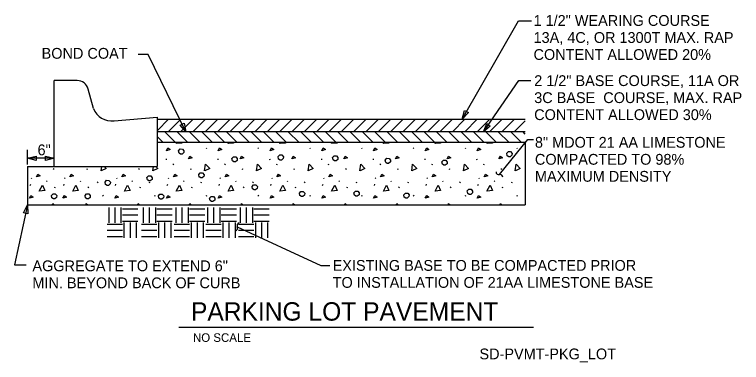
# Model space of a CAD drawing. Extents: x 9880 to 9950.2, y 9968.4 to 10002.
import ezdxf

# ---------------------------------------------------------------- set-up
doc = ezdxf.new("R2010")
doc.units = 0
for name, color, linetype in [('Default', 7, 'Continuous'), ('G-ANNO-TEXT', 7, 'Continuous'), ('G-DETL-LINE', 7, 'Continuous'), ('G-DETL-OTLN', 7, 'Continuous'), ('G-DETL-PATT', 7, 'Continuous')]:
    doc.layers.add(name, color=color, linetype=linetype)

# ---------------------------------------------------------------- blocks, each defined once
blk = doc.blocks.new('TERARR')
at = {"layer": 'Default'}
blk.add_lwpolyline([(-0.667, 0.167), (0, 0), (-0.667, -0.167)], close=True, dxfattribs=at)

msp = doc.modelspace()

# ---------------------------------------------------------------- linework, layer by layer
at = {"layer": 'G-ANNO-TEXT'}
for p, q in [((9881.221, 9987.543), (9881.221, 9988.941)), ((9883.799, 9988.139), (9881.22, 9988.139)), ((9895.832, 9971.824), (9930.089, 9971.824))]:
    msp.add_line(p, q, dxfattribs=at)
for points in [[(9923.211, 9991.928), (9928.665, 10001.42), (9929.9, 10001.42)], [(9896.528, 9990.678), (9892.894, 9998.162), (9891.91, 9998.162)], [(9925.285, 9990.677), (9928.691, 9995.651), (9929.853, 9995.651)]]:
    msp.add_lwpolyline(points, dxfattribs=at)
for points in [[(9923.807, 9992.546), (9923.211, 9991.928), (9923.446, 9992.754)], [(9896.352, 9991.519), (9896.528, 9990.678), (9895.977, 9991.337)], [(9925.927, 9991.247), (9925.285, 9990.677), (9925.584, 9991.483)]]:
    msp.add_lwpolyline(points, close=True, dxfattribs=at)
at = {"layer": 'G-DETL-LINE'}
for p, q in [((9893.766, 9991.898), (9929.301, 9991.898)), ((9929.301, 9990.678), (9893.766, 9990.678)), ((9929.301, 9989.646), (9893.766, 9989.646)), ((9929.301, 9989.646), (9929.301, 9983.643)), ((9881.221, 9987.336), (9883.811, 9987.343)), ((9881.221, 9987.336), (9881.221, 9983.637)), ((9881.234, 9983.643), (9929.301, 9983.643))]:
    msp.add_line(p, q, dxfattribs=at)
for points in [[(9926.807, 9986.558), (9929.565, 9989.95), (9930.084, 9989.95)], [(9881.221, 9983.637), (9879.972, 9977.829), (9881.089, 9977.829)], [(9901.491, 9981.502), (9909.552, 9977.758), (9910.411, 9977.758)]]:
    msp.add_lwpolyline(points, dxfattribs=at)
msp.add_lwpolyline([(9880.842, 9982.866), (9881.221, 9983.637), (9881.249, 9982.778)], close=True, dxfattribs=at)
msp.add_lwpolyline([(9880.842, 9982.866), (9881.221, 9983.637), (9881.249, 9982.778)], close=True, dxfattribs=at)
for centre, start, end in [((9926.744, 9986.811), 177.75583, 284.01603), ((9926.87, 9986.305), 357.75583, 104.01603), ((9901.72, 9981.625), 101.95462, 208.21482), ((9901.261, 9981.379), 281.95462, 28.21482)]:
    msp.add_arc(centre, 0.26, start, end, dxfattribs=at)
at = {"layer": 'G-DETL-OTLN'}
for p, q in [((9886.017, 9995.637), (9883.811, 9995.637)), ((9883.811, 9987.343), (9883.811, 9995.637)), ((9887.605, 9992.951), (9887.082, 9994.828)), ((9889.593, 9991.765), (9893.764, 9992.112)), ((9893.764, 9992.112), (9893.764, 9987.343)), ((9883.811, 9987.343), (9893.764, 9987.343))]:
    msp.add_line(p, q, dxfattribs=at)
for centre, radius, start, end in [((9886.017, 9994.531), 1.106, 15.57142, 90), ((9889.317, 9993.56), 1.816, 199.56291, 278.7552)]:
    msp.add_arc(centre, radius, start, end, dxfattribs=at)
at = {"layer": 'G-DETL-PATT'}
for p, q in [((9893.766, 9990.82), (9894.843, 9991.898)), ((9894.817, 9990.678), (9896.037, 9991.898)), ((9896.01, 9990.678), (9897.23, 9991.898)), ((9897.203, 9990.678), (9898.423, 9991.898)), ((9898.397, 9990.678), (9899.616, 9991.898)), ((9899.59, 9990.678), (9900.809, 9991.898)), ((9900.783, 9990.678), (9902.002, 9991.898)), ((9901.976, 9990.678), (9903.196, 9991.898)), ((9903.169, 9990.678), (9904.389, 9991.898)), ((9904.362, 9990.678), (9905.582, 9991.898)), ((9905.556, 9990.678), (9906.775, 9991.898)), ((9906.749, 9990.678), (9907.968, 9991.898)), ((9907.942, 9990.678), (9909.161, 9991.898)), ((9909.135, 9990.678), (9910.355, 9991.898)), ((9910.328, 9990.678), (9911.548, 9991.898)), ((9911.521, 9990.678), (9912.741, 9991.898)), ((9912.714, 9990.678), (9913.934, 9991.898)), ((9913.908, 9990.678), (9915.127, 9991.898)), ((9915.101, 9990.678), (9916.32, 9991.898)), ((9916.294, 9990.678), (9917.514, 9991.898)), ((9917.487, 9990.678), (9918.707, 9991.898)), ((9918.68, 9990.678), (9919.9, 9991.898)), ((9919.873, 9990.678), (9921.093, 9991.898)), ((9921.066, 9990.678), (9922.286, 9991.898)), ((9922.26, 9990.678), (9923.479, 9991.898)), ((9923.453, 9990.678), (9924.672, 9991.898)), ((9924.646, 9990.678), (9925.866, 9991.898)), ((9925.839, 9990.678), (9927.059, 9991.898)), ((9927.032, 9990.678), (9928.252, 9991.898)), ((9928.225, 9990.678), (9929.301, 9991.753)), ((9894.325, 9989.646), (9893.766, 9990.206)), ((9895.518, 9989.646), (9894.486, 9990.678)), ((9896.712, 9989.646), (9895.679, 9990.678)), ((9897.905, 9989.646), (9896.873, 9990.678)), ((9899.098, 9989.646), (9898.066, 9990.678)), ((9900.291, 9989.646), (9899.259, 9990.678)), ((9901.484, 9989.646), (9900.452, 9990.678)), ((9902.677, 9989.646), (9901.645, 9990.678)), ((9903.871, 9989.646), (9902.838, 9990.678)), ((9905.064, 9989.646), (9904.032, 9990.678)), ((9906.257, 9989.646), (9905.225, 9990.678)), ((9907.45, 9989.646), (9906.418, 9990.678)), ((9908.643, 9989.646), (9907.611, 9990.678)), ((9909.836, 9989.646), (9908.804, 9990.678)), ((9911.03, 9989.646), (9909.997, 9990.678)), ((9912.223, 9989.646), (9911.19, 9990.678)), ((9913.416, 9989.646), (9912.384, 9990.678)), ((9914.609, 9989.646), (9913.577, 9990.678)), ((9915.802, 9989.646), (9914.77, 9990.678)), ((9916.995, 9989.646), (9915.963, 9990.678)), ((9918.188, 9989.646), (9917.156, 9990.678)), ((9919.382, 9989.646), (9918.349, 9990.678)), ((9920.575, 9989.646), (9919.543, 9990.678)), ((9921.768, 9989.646), (9920.736, 9990.678)), ((9922.961, 9989.646), (9921.929, 9990.678)), ((9924.154, 9989.646), (9923.122, 9990.678)), ((9925.347, 9989.646), (9924.315, 9990.678)), ((9926.541, 9989.646), (9925.508, 9990.678)), ((9927.734, 9989.646), (9926.701, 9990.678)), ((9928.927, 9989.646), (9927.895, 9990.678)), ((9929.301, 9990.465), (9929.088, 9990.678)), ((9898.484, 9989.147), (9898.528, 9989.08)), ((9903.484, 9989.147), (9903.528, 9989.08)), ((9908.484, 9989.147), (9908.528, 9989.08)), ((9913.484, 9989.147), (9913.528, 9989.08)), ((9918.484, 9989.147), (9918.528, 9989.08)), ((9923.484, 9989.147), (9923.528, 9989.08)), ((9928.484, 9989.147), (9928.528, 9989.08)), ((9894.606, 9988.082), (9894.617, 9987.982)), ((9895.298, 9987.493), (9895.343, 9987.593)), ((9899.606, 9988.082), (9899.617, 9987.982)), ((9900.298, 9987.493), (9900.343, 9987.593)), ((9904.606, 9988.082), (9904.617, 9987.982)), ((9905.298, 9987.493), (9905.343, 9987.593)), ((9909.606, 9988.082), (9909.617, 9987.982)), ((9910.298, 9987.493), (9910.343, 9987.593)), ((9914.606, 9988.082), (9914.617, 9987.982)), ((9915.298, 9987.493), (9915.343, 9987.593)), ((9919.606, 9988.082), (9919.617, 9987.982)), ((9920.298, 9987.493), (9920.343, 9987.593)), ((9924.606, 9988.082), (9924.617, 9987.982)), ((9925.298, 9987.493), (9925.343, 9987.593)), ((9883.75, 9987.038), (9883.795, 9987.138)), ((9886.985, 9987.038), (9887.03, 9987.138)), ((9891.985, 9987.038), (9892.03, 9987.138)), ((9896.985, 9987.038), (9897.03, 9987.138)), ((9901.985, 9987.038), (9902.03, 9987.138)), ((9906.985, 9987.038), (9907.03, 9987.138)), ((9911.985, 9987.038), (9912.03, 9987.138)), ((9916.985, 9987.038), (9917.03, 9987.138)), ((9921.985, 9987.038), (9922.03, 9987.138)), ((9926.985, 9987.038), (9927.03, 9987.138)), ((9881.576, 9986.25), (9881.621, 9986.183)), ((9884.811, 9986.25), (9884.856, 9986.183)), ((9889.811, 9986.25), (9889.856, 9986.183)), ((9894.811, 9986.25), (9894.856, 9986.183)), ((9899.811, 9986.25), (9899.856, 9986.183)), ((9904.811, 9986.25), (9904.856, 9986.183)), ((9909.811, 9986.25), (9909.856, 9986.183)), ((9914.811, 9986.25), (9914.856, 9986.183)), ((9919.811, 9986.25), (9919.856, 9986.183)), ((9924.811, 9986.25), (9924.856, 9986.183)), ((9881.492, 9985.518), (9881.537, 9985.618)), ((9883.072, 9985.967), (9883.116, 9985.901)), ((9883.861, 9985.263), (9883.906, 9985.363)), ((9884.727, 9985.518), (9884.772, 9985.618)), ((9886.306, 9985.967), (9886.351, 9985.901)), ((9887.096, 9985.263), (9887.141, 9985.363)), ((9887.995, 9985.75), (9888.04, 9985.85)), ((9889.727, 9985.518), (9889.772, 9985.618)), ((9891.306, 9985.967), (9891.351, 9985.901)), ((9892.096, 9985.263), (9892.141, 9985.363)), ((9892.995, 9985.75), (9893.04, 9985.85)), ((9894.727, 9985.518), (9894.772, 9985.618)), ((9896.306, 9985.967), (9896.351, 9985.901)), ((9897.096, 9985.263), (9897.141, 9985.363)), ((9897.995, 9985.75), (9898.04, 9985.85)), ((9899.727, 9985.518), (9899.772, 9985.618)), ((9901.306, 9985.967), (9901.351, 9985.901)), ((9902.096, 9985.263), (9902.141, 9985.363)), ((9902.995, 9985.75), (9903.04, 9985.85)), ((9904.727, 9985.518), (9904.772, 9985.618)), ((9906.306, 9985.967), (9906.351, 9985.901)), ((9907.096, 9985.263), (9907.141, 9985.363)), ((9907.995, 9985.75), (9908.04, 9985.85)), ((9909.727, 9985.518), (9909.772, 9985.618)), ((9911.306, 9985.967), (9911.351, 9985.901)), ((9912.096, 9985.263), (9912.141, 9985.363)), ((9912.995, 9985.75), (9913.04, 9985.85)), ((9914.727, 9985.518), (9914.772, 9985.618)), ((9916.306, 9985.967), (9916.351, 9985.901)), ((9917.096, 9985.263), (9917.141, 9985.363)), ((9917.995, 9985.75), (9918.04, 9985.85)), ((9919.727, 9985.518), (9919.772, 9985.618)), ((9921.306, 9985.967), (9921.351, 9985.901)), ((9922.096, 9985.263), (9922.141, 9985.363)), ((9922.995, 9985.75), (9923.04, 9985.85)), ((9924.727, 9985.518), (9924.772, 9985.618)), ((9926.306, 9985.967), (9926.351, 9985.901)), ((9927.096, 9985.263), (9927.141, 9985.363)), ((9927.995, 9985.75), (9928.04, 9985.85)), ((9888.484, 9984.553), (9888.528, 9984.486)), ((9893.484, 9984.553), (9893.528, 9984.486)), ((9898.484, 9984.553), (9898.528, 9984.486)), ((9903.484, 9984.553), (9903.528, 9984.486)), ((9908.484, 9984.553), (9908.528, 9984.486)), ((9913.484, 9984.553), (9913.528, 9984.486)), ((9918.484, 9984.553), (9918.528, 9984.486)), ((9923.484, 9984.553), (9923.528, 9984.486)), ((9928.484, 9984.553), (9928.528, 9984.486)), ((9889.069, 9983.389), (9889.069, 9981.907)), ((9889.662, 9983.389), (9889.662, 9981.907)), ((9890.255, 9983.389), (9890.255, 9981.907)), ((9890.392, 9983.252), (9891.874, 9983.252)), ((9892.399, 9983.389), (9892.399, 9981.907)), ((9892.992, 9983.389), (9892.992, 9981.907)), ((9893.585, 9983.389), (9893.585, 9981.907)), ((9893.722, 9983.252), (9895.205, 9983.252)), ((9895.549, 9983.389), (9895.549, 9981.907)), ((9896.142, 9983.389), (9896.142, 9981.907)), ((9896.735, 9983.389), (9896.735, 9981.907)), ((9896.872, 9983.252), (9898.355, 9983.252)), ((9898.609, 9983.389), (9898.609, 9981.907)), ((9899.202, 9983.389), (9899.202, 9981.907)), ((9899.795, 9983.389), (9899.795, 9981.907)), ((9899.933, 9983.252), (9901.415, 9983.252)), ((9901.76, 9983.389), (9901.76, 9981.907)), ((9902.353, 9983.389), (9902.353, 9981.907)), ((9902.946, 9983.389), (9902.946, 9981.907)), ((9903.083, 9983.252), (9904.565, 9983.252)), ((9890.392, 9982.659), (9891.874, 9982.659)), ((9893.722, 9982.659), (9895.205, 9982.659)), ((9896.872, 9982.659), (9898.355, 9982.659)), ((9899.933, 9982.659), (9901.415, 9982.659)), ((9903.083, 9982.659), (9904.565, 9982.659)), ((9890.392, 9982.066), (9891.874, 9982.066)), ((9890.54, 9981.917), (9890.54, 9980.435)), ((9891.133, 9981.917), (9891.133, 9980.435)), ((9891.726, 9981.917), (9891.726, 9980.435)), ((9893.722, 9982.066), (9895.205, 9982.066)), ((9893.87, 9981.917), (9893.87, 9980.435)), ((9894.463, 9981.917), (9894.463, 9980.435)), ((9895.056, 9981.917), (9895.056, 9980.435)), ((9896.872, 9982.066), (9898.355, 9982.066)), ((9897.021, 9981.917), (9897.021, 9980.435)), ((9897.614, 9981.917), (9897.614, 9980.435)), ((9898.207, 9981.917), (9898.207, 9980.435)), ((9899.933, 9982.066), (9901.415, 9982.066)), ((9900.081, 9981.917), (9900.081, 9980.435)), ((9900.674, 9981.917), (9900.674, 9980.435)), ((9901.267, 9981.917), (9901.267, 9980.435)), ((9903.083, 9982.066), (9904.565, 9982.066)), ((9903.231, 9981.917), (9903.231, 9980.435)), ((9903.824, 9981.917), (9903.824, 9980.435)), ((9904.417, 9981.917), (9904.417, 9980.435)), ((9888.909, 9981.769), (9890.392, 9981.769)), ((9888.909, 9981.176), (9890.392, 9981.176)), ((9892.24, 9981.769), (9893.722, 9981.769)), ((9892.24, 9981.176), (9893.722, 9981.176)), ((9895.39, 9981.769), (9896.872, 9981.769)), ((9895.39, 9981.176), (9896.872, 9981.176)), ((9898.45, 9981.769), (9899.933, 9981.769)), ((9898.45, 9981.176), (9899.933, 9981.176)), ((9901.6, 9981.769), (9903.083, 9981.769)), ((9901.6, 9981.176), (9903.083, 9981.176)), ((9888.909, 9980.583), (9890.392, 9980.583)), ((9892.24, 9980.583), (9893.722, 9980.583)), ((9895.39, 9980.583), (9896.872, 9980.583)), ((9898.45, 9980.583), (9899.933, 9980.583)), ((9901.6, 9980.583), (9903.083, 9980.583))]:
    msp.add_line(p, q, dxfattribs=at)
for points in [[(9895.598, 9989.557), (9895.645, 9989.646)], [(9896.111, 9989.646), (9896.131, 9989.602), (9895.609, 9989.557)], [(9900.598, 9989.557), (9900.645, 9989.646)], [(9901.111, 9989.646), (9901.131, 9989.602), (9900.609, 9989.557)], [(9905.598, 9989.557), (9905.645, 9989.646)], [(9906.111, 9989.646), (9906.131, 9989.602), (9905.609, 9989.557)], [(9910.598, 9989.557), (9910.645, 9989.646)], [(9911.111, 9989.646), (9911.131, 9989.602), (9910.609, 9989.557)], [(9915.598, 9989.557), (9915.645, 9989.646)], [(9916.111, 9989.646), (9916.131, 9989.602), (9915.609, 9989.557)], [(9920.598, 9989.557), (9920.645, 9989.646)], [(9921.111, 9989.646), (9921.131, 9989.602), (9920.609, 9989.557)], [(9925.598, 9989.557), (9925.645, 9989.646)], [(9926.111, 9989.646), (9926.131, 9989.602), (9925.609, 9989.557)], [(9894.649, 9988.858), (9894.783, 9989.136), (9895.005, 9988.969), (9894.649, 9988.858)], [(9895.862, 9988.631), (9895.821, 9988.867), (9895.967, 9989.031), (9896.187, 9989.027), (9896.329, 9988.855), (9896.313, 9988.679), (9896.148, 9988.537), (9896.006, 9988.534), (9895.862, 9988.631)], [(9899.649, 9988.858), (9899.783, 9989.136), (9900.005, 9988.969), (9899.649, 9988.858)], [(9904.649, 9988.858), (9904.783, 9989.136), (9905.005, 9988.969), (9904.649, 9988.858)], [(9909.649, 9988.858), (9909.783, 9989.136), (9910.005, 9988.969), (9909.649, 9988.858)], [(9914.649, 9988.858), (9914.783, 9989.136), (9915.005, 9988.969), (9914.649, 9988.858)], [(9919.649, 9988.858), (9919.783, 9989.136), (9920.005, 9988.969), (9919.649, 9988.858)], [(9924.649, 9988.858), (9924.783, 9989.136), (9925.005, 9988.969), (9924.649, 9988.858)], [(9896.766, 9988.065), (9896.899, 9988.342), (9897.121, 9988.176), (9896.766, 9988.065)], [(9901.014, 9987.874), (9900.973, 9988.11), (9901.119, 9988.274), (9901.339, 9988.27), (9901.48, 9988.098), (9901.464, 9987.922), (9901.3, 9987.78), (9901.157, 9987.778), (9901.014, 9987.874)], [(9901.766, 9988.065), (9901.899, 9988.342), (9902.121, 9988.176), (9901.766, 9988.065)], [(9905.481, 9988.055), (9905.44, 9988.29), (9905.586, 9988.455), (9905.806, 9988.451), (9905.948, 9988.278), (9905.932, 9988.102), (9905.767, 9987.96), (9905.625, 9987.958), (9905.481, 9988.055)], [(9906.766, 9988.065), (9906.899, 9988.342), (9907.121, 9988.176), (9906.766, 9988.065)], [(9910.741, 9987.982), (9910.699, 9988.218), (9910.846, 9988.383), (9911.066, 9988.379), (9911.207, 9988.206), (9911.191, 9988.03), (9911.027, 9987.888), (9910.884, 9987.886), (9910.741, 9987.983)], [(9911.766, 9988.065), (9911.899, 9988.342), (9912.121, 9988.176), (9911.766, 9988.065)], [(9915.82, 9987.73), (9915.779, 9987.966), (9915.926, 9988.13), (9916.146, 9988.126), (9916.287, 9987.954), (9916.271, 9987.778), (9916.106, 9987.636), (9915.964, 9987.633), (9915.82, 9987.73)], [(9916.766, 9988.065), (9916.899, 9988.342), (9917.121, 9988.176), (9916.766, 9988.065)], [(9921.766, 9988.065), (9921.899, 9988.342), (9922.121, 9988.176), (9921.766, 9988.065)], [(9926.766, 9988.065), (9926.899, 9988.342), (9927.121, 9988.176), (9926.766, 9988.065)], [(9927.565, 9988.379), (9927.523, 9988.615), (9927.67, 9988.779), (9927.89, 9988.775), (9928.031, 9988.603), (9928.015, 9988.427), (9927.851, 9988.284), (9927.708, 9988.282), (9927.565, 9988.379)], [(9898.336, 9986.923), (9898.424, 9987.557), (9898.821, 9987.147), (9898.346, 9986.927)], [(9903.336, 9986.923), (9903.424, 9987.557), (9903.821, 9987.147), (9903.346, 9986.927)], [(9908.336, 9986.923), (9908.424, 9987.557), (9908.821, 9987.147), (9908.346, 9986.927)], [(9913.336, 9986.923), (9913.424, 9987.557), (9913.821, 9987.147), (9913.346, 9986.927)], [(9918.336, 9986.923), (9918.424, 9987.557), (9918.821, 9987.147), (9918.346, 9986.927)], [(9921.296, 9987.55), (9921.255, 9987.786), (9921.401, 9987.95), (9921.622, 9987.946), (9921.763, 9987.774), (9921.747, 9987.598), (9921.582, 9987.455), (9921.44, 9987.453), (9921.296, 9987.55)], [(9923.336, 9986.923), (9923.424, 9987.557), (9923.821, 9987.147), (9923.346, 9986.927)], [(9928.336, 9986.923), (9928.424, 9987.557), (9928.821, 9987.147), (9928.346, 9986.927)], [(9888.336, 9986.923), (9888.394, 9987.343)], [(9888.632, 9987.343), (9888.821, 9987.147), (9888.346, 9986.927)], [(9893.336, 9986.923), (9893.394, 9987.343)], [(9893.632, 9987.343), (9893.821, 9987.147), (9893.346, 9986.927)], [(9897.807, 9986.324), (9897.766, 9986.56), (9897.913, 9986.725), (9898.133, 9986.721), (9898.274, 9986.548), (9898.258, 9986.372), (9898.093, 9986.23), (9897.951, 9986.228), (9897.807, 9986.325)], [(9882.085, 9986.327), (9882.219, 9986.605), (9882.441, 9986.438), (9882.085, 9986.327)], [(9885.32, 9986.327), (9885.454, 9986.605), (9885.676, 9986.438), (9885.32, 9986.327)], [(9888.765, 9985.604), (9888.724, 9985.839), (9888.87, 9986.004), (9889.09, 9986), (9889.232, 9985.827), (9889.216, 9985.651), (9889.051, 9985.509), (9888.909, 9985.507), (9888.765, 9985.604)], [(9890.32, 9986.327), (9890.454, 9986.605), (9890.676, 9986.438), (9890.32, 9986.327)], [(9892.8, 9986.036), (9892.759, 9986.272), (9892.905, 9986.436), (9893.125, 9986.432), (9893.267, 9986.26), (9893.25, 9986.084), (9893.086, 9985.941), (9892.944, 9985.939), (9892.8, 9986.036)], [(9895.32, 9986.327), (9895.454, 9986.605), (9895.676, 9986.438), (9895.32, 9986.327)], [(9900.32, 9986.327), (9900.454, 9986.605), (9900.676, 9986.438), (9900.32, 9986.327)], [(9905.32, 9986.327), (9905.454, 9986.605), (9905.676, 9986.438), (9905.32, 9986.327)], [(9910.32, 9986.327), (9910.454, 9986.605), (9910.676, 9986.438), (9910.32, 9986.327)], [(9915.32, 9986.327), (9915.454, 9986.605), (9915.676, 9986.438), (9915.32, 9986.327)], [(9920.32, 9986.327), (9920.454, 9986.605), (9920.676, 9986.438), (9920.32, 9986.327)], [(9925.32, 9986.327), (9925.454, 9986.605), (9925.676, 9986.438), (9925.32, 9986.327)], [(9882.363, 9984.963), (9882.663, 9985.529), (9882.896, 9985.008), (9882.374, 9984.963)], [(9885.598, 9984.963), (9885.898, 9985.529), (9886.131, 9985.008), (9885.609, 9984.963)], [(9890.598, 9984.963), (9890.898, 9985.529), (9891.131, 9985.008), (9890.609, 9984.963)], [(9895.598, 9984.963), (9895.898, 9985.529), (9896.131, 9985.008), (9895.609, 9984.963)], [(9900.598, 9984.963), (9900.898, 9985.529), (9901.131, 9985.008), (9900.609, 9984.963)], [(9902.959, 9985.171), (9902.918, 9985.407), (9903.064, 9985.571), (9903.284, 9985.567), (9903.426, 9985.395), (9903.41, 9985.219), (9903.245, 9985.076), (9903.103, 9985.074), (9902.959, 9985.171)], [(9905.598, 9984.963), (9905.898, 9985.529), (9906.131, 9985.008), (9905.609, 9984.963)], [(9910.598, 9984.963), (9910.898, 9985.529), (9911.131, 9985.008), (9910.609, 9984.963)], [(9915.598, 9984.963), (9915.898, 9985.529), (9916.131, 9985.008), (9915.609, 9984.963)], [(9920.598, 9984.963), (9920.898, 9985.529), (9921.131, 9985.008), (9920.609, 9984.963)], [(9925.598, 9984.963), (9925.898, 9985.529), (9926.131, 9985.008), (9925.609, 9984.963)], [(9883.584, 9984.306), (9883.543, 9984.542), (9883.69, 9984.706), (9883.91, 9984.702), (9884.051, 9984.53), (9884.035, 9984.354), (9883.871, 9984.211), (9883.728, 9984.209), (9883.585, 9984.306)], [(9886.819, 9984.306), (9886.778, 9984.542), (9886.925, 9984.706), (9887.145, 9984.702), (9887.286, 9984.53), (9887.27, 9984.354), (9887.106, 9984.211), (9886.963, 9984.209), (9886.82, 9984.306)], [(9893.917, 9984.27), (9893.875, 9984.506), (9894.022, 9984.67), (9894.242, 9984.666), (9894.383, 9984.494), (9894.367, 9984.318), (9894.203, 9984.175), (9894.06, 9984.173), (9893.917, 9984.27)], [(9907.534, 9984.522), (9907.493, 9984.758), (9907.64, 9984.922), (9907.86, 9984.918), (9908.001, 9984.746), (9907.985, 9984.57), (9907.82, 9984.428), (9907.678, 9984.425), (9907.534, 9984.522)], [(9912.794, 9984.558), (9912.753, 9984.794), (9912.899, 9984.958), (9913.12, 9984.954), (9913.261, 9984.782), (9913.245, 9984.606), (9913.08, 9984.464), (9912.938, 9984.462), (9912.794, 9984.558)], [(9917.621, 9984.378), (9917.58, 9984.614), (9917.727, 9984.778), (9917.947, 9984.774), (9918.088, 9984.602), (9918.072, 9984.426), (9917.908, 9984.283), (9917.765, 9984.281), (9917.622, 9984.378)], [(9923.746, 9984.738), (9923.705, 9984.974), (9923.851, 9985.139), (9924.071, 9985.135), (9924.213, 9984.962), (9924.197, 9984.786), (9924.032, 9984.644), (9923.89, 9984.642), (9923.746, 9984.739)], [(9881.415, 9984.264), (9881.548, 9984.541), (9881.77, 9984.375), (9881.415, 9984.264)], [(9884.649, 9984.264), (9884.783, 9984.541), (9885.005, 9984.375), (9884.649, 9984.264)], [(9889.649, 9984.264), (9889.783, 9984.541), (9890.005, 9984.375), (9889.649, 9984.264)], [(9894.649, 9984.264), (9894.783, 9984.541), (9895.005, 9984.375), (9894.649, 9984.264)], [(9898.852, 9984.054), (9898.811, 9984.29), (9898.957, 9984.454), (9899.178, 9984.45), (9899.319, 9984.277), (9899.303, 9984.101), (9899.138, 9983.959), (9898.996, 9983.957), (9898.852, 9984.054)], [(9899.649, 9984.264), (9899.783, 9984.541), (9900.005, 9984.375), (9899.649, 9984.264)], [(9904.649, 9984.264), (9904.783, 9984.541), (9905.005, 9984.375), (9904.649, 9984.264)], [(9909.649, 9984.264), (9909.783, 9984.541), (9910.005, 9984.375), (9909.649, 9984.264)], [(9914.649, 9984.264), (9914.783, 9984.541), (9915.005, 9984.375), (9914.649, 9984.264)], [(9919.649, 9984.264), (9919.783, 9984.541), (9920.005, 9984.375), (9919.649, 9984.264)], [(9924.649, 9984.264), (9924.783, 9984.541), (9925.005, 9984.375), (9924.649, 9984.264)], [(9883.613, 9983.643), (9883.664, 9983.748), (9883.804, 9983.643)], [(9886.848, 9983.643), (9886.899, 9983.748), (9887.039, 9983.643)], [(9891.848, 9983.643), (9891.899, 9983.748), (9892.039, 9983.643)], [(9896.848, 9983.643), (9896.899, 9983.748), (9897.039, 9983.643)], [(9901.848, 9983.643), (9901.899, 9983.748), (9902.039, 9983.643)], [(9906.848, 9983.643), (9906.899, 9983.748), (9907.039, 9983.643)], [(9911.848, 9983.643), (9911.899, 9983.748), (9912.039, 9983.643)], [(9916.848, 9983.643), (9916.899, 9983.748), (9917.039, 9983.643)], [(9921.848, 9983.643), (9921.899, 9983.748), (9922.039, 9983.643)], [(9926.848, 9983.643), (9926.899, 9983.748), (9927.039, 9983.643)]]:
    msp.add_lwpolyline(points, dxfattribs=at)

# ---------------------------------------------------------------- block references
at = {"layer": 'G-ANNO-TEXT', "xscale": 1.25, "yscale": 1.25, "rotation": 180}
msp.add_blockref('TERARR', (9881.22, 9988.139), dxfattribs=at)
at = {"layer": 'G-ANNO-TEXT', "xscale": 1.25, "yscale": 1.25}
msp.add_blockref('TERARR', (9883.812, 9988.139), dxfattribs=at)

# ---------------------------------------------------------------- texts
at = {"layer": 'G-ANNO-TEXT'}
for s, height, p in [('1 1/2" WEARING COURSE ', 1.044, (9930.103, 10000.928)), ('13A, 4C, OR 1300T MAX. RAP ', 1.044, (9930.103, 9999.284)), ('BOND COAT', 1.044, (9882.59, 9997.754)), ('CONTENT ALLOWED 20%', 1.044, (9930.103, 9997.64)), ('2 1/2" BASE COURSE, 11A OR ', 1.044, (9930.168, 9995.114)), ('3C BASE  COURSE, MAX. RAP ', 1.044, (9930.168, 9993.47)), ('CONTENT ALLOWED 30%', 1.044, (9930.168, 9991.826)), ('8" MDOT 21 AA LIMESTONE', 1.044, (9930.238, 9989.155)), ('6"', 1.044, (9882.192, 9988.422)), ('COMPACTED TO 98%', 1.044, (9930.238, 9987.511)), ('MAXIMUM DENSITY', 1.044, (9930.238, 9985.867)), ('AGGREGATE TO EXTEND 6"', 1.044, (9881.701, 9977.218)), ('EXISTING BASE TO BE COMPACTED PRIOR ', 1.044, (9910.701, 9977.258)), ('MIN. BEYOND BACK OF CURB', 1.044, (9881.701, 9975.574)), ('TO INSTALLATION OF 21AA LIMESTONE BASE', 1.044, (9910.701, 9975.614)), ('PARKING LOT PAVEMENT', 1.776, (9897.014, 9972.443)), ('NO SCALE', 0.828, (9897.208, 9970.39)), ('SD-PVMT-PKG_LOT', 1.044, (9924.882, 9968.701))]:
    msp.add_text(s, height=height, dxfattribs=at).set_placement(p)

doc.saveas('drawing.dxf')
